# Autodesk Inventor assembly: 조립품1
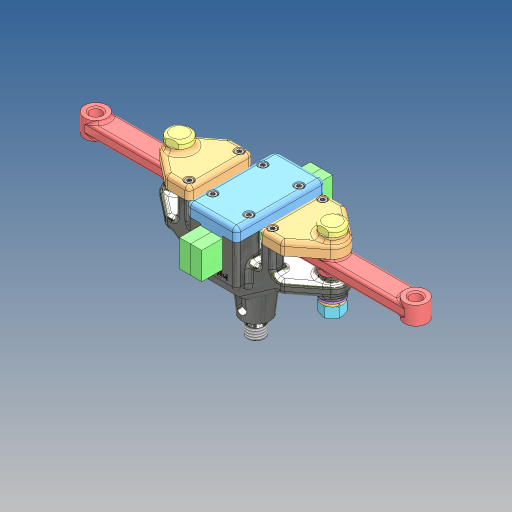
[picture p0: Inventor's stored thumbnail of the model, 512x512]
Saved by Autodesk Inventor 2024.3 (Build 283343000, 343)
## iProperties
Created: 2025-07
Part Number: 조립품1
Document SubType Name: Assembly
Designer: user
Author: user
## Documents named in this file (12)
- C:\Users\user\Desktop\750703V1001\조립품1.iam
- C:\Users\user\Desktop\750703V1001\본체.ipt
- C:\Users\user\Desktop\750703V1001\6각 구멍붙이 볼트 M3x10\6각 구멍붙이 볼트 M3x10.ipt
- C:\Users\user\Desktop\750703V1001\6각 너트 M8\6각 너트 M8.ipt
- C:\Users\user\Desktop\750703V1001\링크 커버\링크 커버.ipt
- C:\Users\user\Desktop\750703V1001\링크\링크.ipt
- C:\Users\user\Desktop\750703V1001\스프링 와셔 M8\스프링 와셔 M8.ipt
- C:\Users\user\Desktop\750703V1001\슬라이더 커버\슬라이더 커버.ipt
- C:\Users\user\Desktop\750703V1001\슬라이더\슬라이더.ipt
- C:\Users\user\Desktop\750703V1001\평 와셔 M8\평 와셔 M8.ipt
- C:\Users\user\Desktop\750703V1001\핀\핀.ipt
- C:\Users\user\Desktop\750703V1001\6각 구멍붙이 볼트 M3x10\6각 구멍붙이 볼트 M3x10_MIR.ipt
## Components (12 placed, 4 different names)
1. 6각 구멍붙이 볼트 M3x10:1
2. 6각 너트 M8:1
3. 핀:1
4. 6각 너트 M8:2
5. 핀:2
6. 6각 구멍붙이 볼트 M3x10:2
7. 6각 구멍붙이 볼트 M3x10:3
8. 6각 구멍붙이 볼트 M3x10:4
9. 6각 구멍붙이 볼트 M3x10_MIR:1
10. 6각 구멍붙이 볼트 M3x10_MIR:2
11. 6각 구멍붙이 볼트 M3x10_MIR:3
12. 6각 구멍붙이 볼트 M3x10_MIR:4
